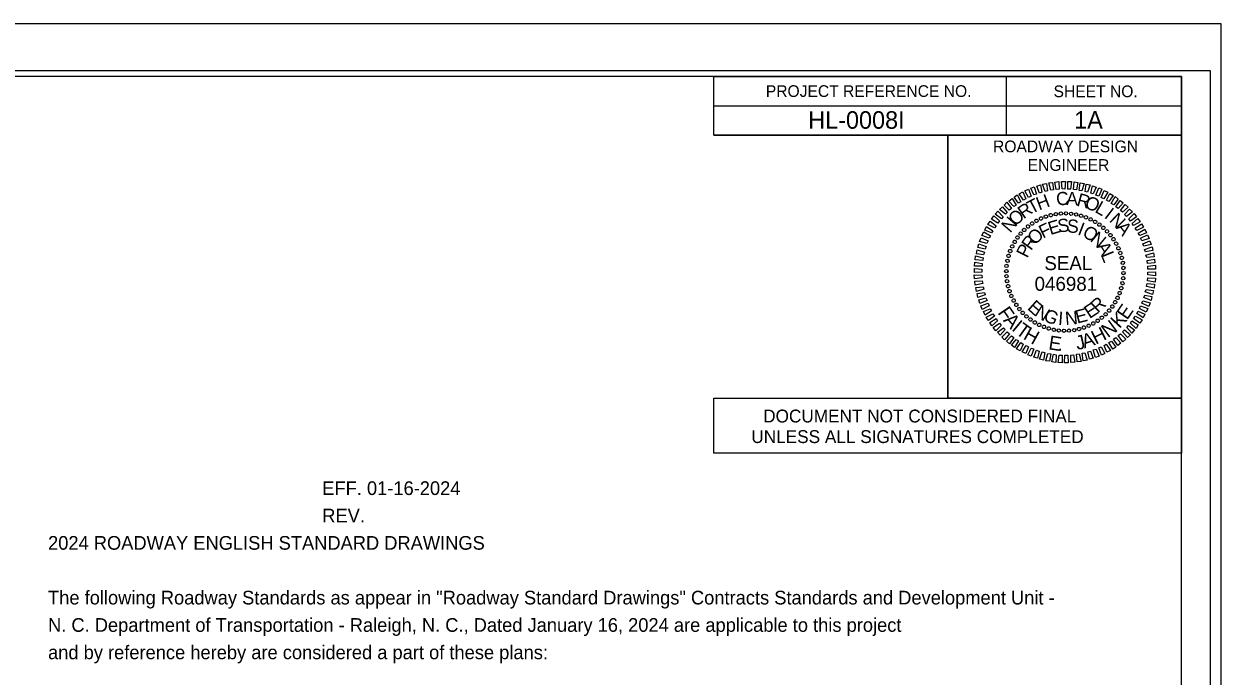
# Model space of a CAD drawing. Extents: x 3312684 to 3314684, y -677777 to -676682.
# Drawn here: x 3314171 to 3314684, y -676961 to -676682 of the extents above; entities that cross this region are included whole.
import ezdxf

# ---------------------------------------------------------------- set-up
doc = ezdxf.new("R2010")
doc.units = 0
for name, color, linetype in [('Default', 7, 'Continuous'), ('Sheet Data Field CELL', 7, 'Continuous'), ('Sheet PE Seal Cell', 7, 'Continuous'), ('Sheet Plan CELL', 7, 'Continuous'), ('Sheet Plot Border Inside CELL', 7, 'Continuous'), ('Sheet Plot Border Outside CELL', 7, 'Continuous'), ('Sheet Sticker Exception Certification CELL', 7, 'Continuous')]:
    doc.layers.add(name, color=color, linetype=linetype)

msp = doc.modelspace()

# ---------------------------------------------------------------- linework, layer by layer
at = {"layer": 'Sheet PE Seal Cell'}
for p, q in [((3314602.85, -676767.34), (3314602.85, -676767.34)), ((3314604.75, -676766.19), (3314604.75, -676766.19)), ((3314606.7, -676765.19), (3314606.7, -676765.19)), ((3314608.7, -676764.39), (3314608.7, -676764.39)), ((3314610.8, -676763.79), (3314610.8, -676763.79)), ((3314613, -676763.39), (3314613, -676763.39)), ((3314615.15, -676763.09), (3314615.15, -676763.09)), ((3314617.35, -676763.04), (3314617.35, -676763.04)), ((3314619.55, -676763.19), (3314619.55, -676763.19)), ((3314621.7, -676763.54), (3314621.7, -676763.54)), ((3314623.8, -676763.99), (3314623.8, -676763.99)), ((3314625.9, -676764.69), (3314625.9, -676764.69)), ((3314627.9, -676765.59), (3314627.9, -676765.59)), ((3314629.85, -676766.59), (3314629.85, -676766.59)), ((3314631.65, -676767.84), (3314631.65, -676767.84)), ((3314597.95, -676771.64), (3314597.95, -676771.64)), ((3314599.45, -676770.09), (3314599.45, -676770.09)), ((3314601.1, -676768.59), (3314601.1, -676768.59)), ((3314633.4, -676769.19), (3314633.4, -676769.19)), ((3314634.95, -676770.69), (3314634.95, -676770.69)), ((3314636.45, -676772.34), (3314636.45, -676772.34)), ((3314594.35, -676777.14), (3314594.35, -676777.14)), ((3314595.35, -676775.19), (3314595.35, -676775.19)), ((3314596.6, -676773.39), (3314596.6, -676773.39)), ((3314637.7, -676774.09), (3314637.7, -676774.09)), ((3314638.85, -676775.99), (3314638.85, -676775.99)), ((3314639.85, -676777.94), (3314639.85, -676777.94)), ((3314592.3, -676783.34), (3314592.3, -676783.34)), ((3314592.75, -676781.24), (3314592.75, -676781.24)), ((3314593.45, -676779.14), (3314593.45, -676779.14)), ((3314640.65, -676779.94), (3314640.65, -676779.94)), ((3314641.25, -676782.04), (3314641.25, -676782.04)), ((3314591.8, -676787.69), (3314591.8, -676787.69)), ((3314591.95, -676785.49), (3314591.95, -676785.49)), ((3314616.9, -676788.14), (3314616.9, -676788.14)), ((3314641.65, -676784.24), (3314641.65, -676784.24)), ((3314641.95, -676786.39), (3314641.95, -676786.39)), ((3314591.85, -676789.89), (3314591.85, -676789.89)), ((3314592.15, -676792.04), (3314592.15, -676792.04)), ((3314641.5, -676792.94), (3314641.5, -676792.94)), ((3314641.85, -676790.79), (3314641.85, -676790.79)), ((3314642, -676788.59), (3314642, -676788.59)), ((3314592.55, -676794.24), (3314592.55, -676794.24)), ((3314593.15, -676796.34), (3314593.15, -676796.34)), ((3314593.95, -676798.34), (3314593.95, -676798.34)), ((3314640.35, -676797.14), (3314640.35, -676797.14)), ((3314641.05, -676795.04), (3314641.05, -676795.04)), ((3314594.95, -676800.29), (3314594.95, -676800.29)), ((3314596.1, -676802.19), (3314596.1, -676802.19)), ((3314637.2, -676802.89), (3314637.2, -676802.89)), ((3314638.45, -676801.09), (3314638.45, -676801.09)), ((3314639.45, -676799.14), (3314639.45, -676799.14)), ((3314597.35, -676803.94), (3314597.35, -676803.94)), ((3314598.85, -676805.59), (3314598.85, -676805.59)), ((3314600.4, -676807.09), (3314600.4, -676807.09)), ((3314602.15, -676808.44), (3314602.15, -676808.44)), ((3314630.95, -676808.94), (3314630.95, -676808.94)), ((3314632.7, -676807.69), (3314632.7, -676807.69)), ((3314634.35, -676806.19), (3314634.35, -676806.19)), ((3314635.85, -676804.64), (3314635.85, -676804.64)), ((3314603.95, -676809.69), (3314603.95, -676809.69)), ((3314605.9, -676810.69), (3314605.9, -676810.69)), ((3314607.9, -676811.59), (3314607.9, -676811.59)), ((3314610, -676812.29), (3314610, -676812.29)), ((3314612.1, -676812.74), (3314612.1, -676812.74)), ((3314614.25, -676813.09), (3314614.25, -676813.09)), ((3314616.45, -676813.24), (3314616.45, -676813.24)), ((3314618.65, -676813.19), (3314618.65, -676813.19)), ((3314620.8, -676812.89), (3314620.8, -676812.89)), ((3314623, -676812.49), (3314623, -676812.49)), ((3314625.1, -676811.89), (3314625.1, -676811.89)), ((3314627.1, -676811.09), (3314627.1, -676811.09)), ((3314629.05, -676810.09), (3314629.05, -676810.09))]:
    msp.add_line(p, q, dxfattribs=at)
for points in [[(3314603.55, -676755.14), (3314602.25, -676752.24), (3314603.75, -676751.64), (3314604.8, -676754.84)], [(3314606, -676754.34), (3314604.85, -676751.34), (3314606.4, -676750.89), (3314607.05, -676753.99)], [(3314608.4, -676753.69), (3314607.35, -676750.54), (3314609.05, -676750.19), (3314609.45, -676753.44)], [(3314610.8, -676753.14), (3314610, -676749.94), (3314611.65, -676749.79), (3314612, -676752.99)], [(3314613.2, -676752.84), (3314612.65, -676749.64), (3314614.35, -676749.44), (3314614.4, -676752.69)], [(3314615.7, -676752.59), (3314615.45, -676749.34), (3314617.1, -676749.39), (3314616.9, -676752.64)], [(3314618.1, -676752.64), (3314618.1, -676749.39), (3314619.75, -676749.44), (3314619.3, -676752.69)], [(3314620.6, -676752.79), (3314620.8, -676749.54), (3314622.45, -676749.84), (3314621.8, -676752.99)], [(3314623, -676753.19), (3314623.45, -676749.99), (3314625.1, -676750.24), (3314624.2, -676753.34)], [(3314625.55, -676753.74), (3314626.05, -676750.49), (3314627.75, -676750.89), (3314626.6, -676753.99)], [(3314627.95, -676754.39), (3314628.7, -676751.29), (3314630.25, -676751.79), (3314629, -676754.74)], [(3314630.2, -676755.29), (3314631.35, -676752.14), (3314632.75, -676752.74), (3314631.35, -676755.64)], [(3314595.1, -676760.14), (3314592.95, -676757.74), (3314594.3, -676756.69), (3314596.05, -676759.49)], [(3314597, -676758.64), (3314595.15, -676756.09), (3314596.45, -676755.14), (3314598.1, -676758.04)], [(3314599.2, -676757.39), (3314597.35, -676754.69), (3314598.9, -676753.89), (3314600.15, -676756.79)], [(3314601.35, -676756.19), (3314599.75, -676753.39), (3314601.3, -676752.69), (3314602.45, -676755.74)], [(3314632.45, -676756.24), (3314633.7, -676753.29), (3314635.25, -676753.99), (3314633.55, -676756.79)], [(3314634.75, -676757.39), (3314636.1, -676754.54), (3314637.6, -676755.39), (3314635.7, -676757.99)], [(3314636.7, -676758.74), (3314638.45, -676755.84), (3314639.75, -676756.89), (3314637.8, -676759.34)], [(3314638.75, -676760.24), (3314640.6, -676757.49), (3314641.9, -676758.59), (3314639.7, -676760.94)], [(3314589.7, -676765.34), (3314587.1, -676763.39), (3314588.2, -676762.09), (3314590.4, -676764.44)], [(3314591.45, -676763.44), (3314588.9, -676761.39), (3314590.15, -676760.24), (3314592.25, -676762.64)], [(3314593.1, -676761.69), (3314590.9, -676759.49), (3314592.1, -676758.29), (3314594.05, -676760.99)], [(3314640.65, -676761.79), (3314642.7, -676759.19), (3314643.9, -676760.39), (3314641.6, -676762.54)], [(3314642.45, -676763.54), (3314644.6, -676761.19), (3314645.8, -676762.39), (3314643.2, -676764.34)], [(3314586.7, -676769.24), (3314583.9, -676767.74), (3314584.9, -676766.34), (3314587.5, -676768.34)], [(3314588.2, -676767.24), (3314585.5, -676765.54), (3314586.45, -676764.09), (3314588.85, -676766.29)], [(3314644.2, -676765.34), (3314646.5, -676763.09), (3314647.55, -676764.44), (3314644.9, -676766.34)], [(3314645.7, -676767.29), (3314648.15, -676765.19), (3314649.1, -676766.64), (3314646.3, -676768.24)], [(3314647, -676769.34), (3314649.65, -676767.44), (3314650.6, -676768.94), (3314647.7, -676770.34)], [(3314584.5, -676773.69), (3314581.4, -676772.54), (3314582.15, -676770.99), (3314585, -676772.59)], [(3314585.5, -676771.39), (3314582.65, -676770.14), (3314583.4, -676768.59), (3314586.1, -676770.44)], [(3314648.3, -676771.54), (3314651.1, -676769.79), (3314651.75, -676771.34), (3314648.9, -676772.49)], [(3314649.3, -676773.69), (3314652.25, -676772.19), (3314652.9, -676773.79), (3314649.8, -676774.79)], [(3314582.75, -676778.29), (3314579.65, -676777.64), (3314580, -676775.99), (3314583.15, -676777.24)], [(3314583.5, -676775.89), (3314580.4, -676774.99), (3314581.05, -676773.44), (3314584.05, -676774.84)], [(3314650.2, -676776.04), (3314653.25, -676774.74), (3314653.8, -676776.29), (3314650.7, -676777.09)], [(3314651, -676778.44), (3314654.2, -676777.29), (3314654.5, -676778.94), (3314651.35, -676779.49)], [(3314581.7, -676783.24), (3314578.5, -676782.94), (3314578.7, -676781.24), (3314581.95, -676782.04)], [(3314582.1, -676780.69), (3314579, -676780.29), (3314579.35, -676778.59), (3314582.5, -676779.64)], [(3314651.6, -676780.84), (3314654.75, -676779.89), (3314655.05, -676781.59), (3314651.9, -676781.89)], [(3314652.05, -676783.24), (3314655.3, -676782.54), (3314655.45, -676784.24), (3314652.25, -676784.44)], [(3314581.4, -676788.14), (3314578.15, -676788.29), (3314578.15, -676786.59), (3314581.4, -676786.94)], [(3314581.45, -676785.64), (3314578.2, -676785.54), (3314578.3, -676783.89), (3314581.55, -676784.44)], [(3314652.35, -676785.64), (3314655.6, -676785.24), (3314655.7, -676786.94), (3314652.45, -676786.84)], [(3314652.4, -676788.14), (3314655.65, -676787.99), (3314655.65, -676789.69), (3314652.4, -676789.34)], [(3314581.45, -676790.64), (3314578.2, -676791.04), (3314578.1, -676789.34), (3314581.35, -676789.44)], [(3314581.75, -676793.04), (3314578.5, -676793.74), (3314578.35, -676792.04), (3314581.55, -676791.84)], [(3314652.1, -676793.04), (3314655.3, -676793.34), (3314655.1, -676795.04), (3314651.85, -676794.24)], [(3314652.35, -676790.64), (3314655.6, -676790.74), (3314655.5, -676792.39), (3314652.25, -676791.84)], [(3314582.2, -676795.44), (3314579.05, -676796.39), (3314578.75, -676794.69), (3314581.9, -676794.39)], [(3314582.8, -676797.84), (3314579.6, -676798.99), (3314579.3, -676797.34), (3314582.45, -676796.79)], [(3314651.05, -676797.99), (3314654.15, -676798.64), (3314653.8, -676800.29), (3314650.65, -676799.04)], [(3314651.7, -676795.59), (3314654.8, -676795.99), (3314654.45, -676797.69), (3314651.3, -676796.64)], [(3314583.6, -676800.24), (3314580.55, -676801.54), (3314580, -676799.99), (3314583.1, -676799.19)], [(3314584.5, -676802.59), (3314581.55, -676804.09), (3314580.9, -676802.49), (3314584, -676801.49)], [(3314585.5, -676804.74), (3314582.7, -676806.49), (3314582.05, -676804.94), (3314584.9, -676803.79)], [(3314649.3, -676802.59), (3314652.4, -676803.74), (3314651.65, -676805.29), (3314648.8, -676803.69)], [(3314650.3, -676800.39), (3314653.4, -676801.29), (3314652.75, -676802.84), (3314649.75, -676801.44)], [(3314586.8, -676806.94), (3314584.15, -676808.84), (3314583.2, -676807.34), (3314586.1, -676805.94)], [(3314588.1, -676808.99), (3314585.65, -676811.09), (3314584.7, -676809.64), (3314587.5, -676808.04)], [(3314645.6, -676809.04), (3314648.3, -676810.74), (3314647.35, -676812.19), (3314644.95, -676809.99)], [(3314647.1, -676807.04), (3314649.9, -676808.54), (3314648.9, -676809.94), (3314646.3, -676807.94)], [(3314648.3, -676804.89), (3314651.15, -676806.14), (3314650.4, -676807.69), (3314647.7, -676805.84)], [(3314589.6, -676810.94), (3314587.3, -676813.19), (3314586.25, -676811.84), (3314588.9, -676809.94)], [(3314591.35, -676812.74), (3314589.2, -676815.09), (3314588, -676813.89), (3314590.6, -676811.94)], [(3314593.15, -676814.49), (3314591.1, -676817.09), (3314589.9, -676815.89), (3314592.2, -676813.74)], [(3314642.35, -676812.84), (3314644.9, -676814.89), (3314643.65, -676816.04), (3314641.55, -676813.64)], [(3314644.1, -676810.94), (3314646.7, -676812.89), (3314645.6, -676814.19), (3314643.4, -676811.84)], [(3314595.05, -676816.04), (3314593.2, -676818.79), (3314591.9, -676817.69), (3314594.1, -676815.34)], [(3314597.1, -676817.54), (3314595.35, -676820.44), (3314594.05, -676819.39), (3314596, -676816.94)], [(3314599.05, -676818.89), (3314597.7, -676821.74), (3314596.2, -676820.89), (3314598.1, -676818.29)], [(3314634.6, -676818.89), (3314636.45, -676821.59), (3314634.9, -676822.39), (3314633.65, -676819.49)], [(3314636.8, -676817.64), (3314638.65, -676820.19), (3314637.35, -676821.14), (3314635.7, -676818.24)], [(3314638.7, -676816.14), (3314640.85, -676818.54), (3314639.5, -676819.59), (3314637.75, -676816.79)], [(3314640.7, -676814.59), (3314642.9, -676816.79), (3314641.7, -676817.99), (3314639.75, -676815.29)], [(3314601.35, -676820.04), (3314600.1, -676822.99), (3314598.55, -676822.29), (3314600.25, -676819.49)], [(3314603.6, -676820.99), (3314602.45, -676824.14), (3314601.05, -676823.54), (3314602.45, -676820.64)], [(3314605.85, -676821.89), (3314605.1, -676824.99), (3314603.55, -676824.49), (3314604.8, -676821.54)], [(3314608.25, -676822.54), (3314607.75, -676825.79), (3314606.05, -676825.39), (3314607.2, -676822.29)], [(3314610.8, -676823.09), (3314610.35, -676826.29), (3314608.7, -676826.04), (3314609.6, -676822.94)], [(3314613.2, -676823.49), (3314613, -676826.74), (3314611.35, -676826.44), (3314612, -676823.29)], [(3314615.7, -676823.64), (3314615.7, -676826.89), (3314614.05, -676826.84), (3314614.5, -676823.59)], [(3314618.1, -676823.69), (3314618.35, -676826.94), (3314616.7, -676826.89), (3314616.9, -676823.64)], [(3314620.6, -676823.44), (3314621.15, -676826.64), (3314619.45, -676826.84), (3314619.4, -676823.59)], [(3314623, -676823.14), (3314623.8, -676826.34), (3314622.15, -676826.49), (3314621.8, -676823.29)], [(3314625.4, -676822.59), (3314626.45, -676825.74), (3314624.75, -676826.09), (3314624.35, -676822.84)], [(3314627.8, -676821.94), (3314628.95, -676824.94), (3314627.4, -676825.39), (3314626.75, -676822.29)], [(3314630.25, -676821.14), (3314631.55, -676824.04), (3314630.05, -676824.64), (3314629, -676821.44)], [(3314632.45, -676820.09), (3314634.05, -676822.89), (3314632.5, -676823.59), (3314631.35, -676820.54)]]:
    msp.add_lwpolyline(points, close=True, dxfattribs=at)
for centre, major_axis in [((3314612.97, -676763.37), (-0.113, 0.711)), ((3314615.15, -676763.12), (-0.05, 0.718)), ((3314617.33, -676763.06), (0.013, 0.72)), ((3314619.52, -676763.19), (0.075, 0.716)), ((3314621.68, -676763.52), (0.137, 0.707)), ((3314601.11, -676768.65), (-0.453, 0.56)), ((3314602.87, -676767.34), (-0.403, 0.597)), ((3314604.74, -676766.2), (-0.349, 0.63)), ((3314606.69, -676765.22), (-0.293, 0.658)), ((3314608.73, -676764.42), (-0.234, 0.681)), ((3314610.83, -676763.8), (-0.174, 0.699)), ((3314623.81, -676764.03), (0.198, 0.692)), ((3314625.88, -676764.72), (0.258, 0.672)), ((3314627.89, -676765.59), (0.316, 0.647)), ((3314629.81, -676766.64), (0.371, 0.617)), ((3314631.64, -676767.85), (0.423, 0.582)), ((3314596.61, -676773.39), (-0.582, 0.423)), ((3314597.97, -676771.68), (-0.543, 0.472)), ((3314599.47, -676770.1), (-0.5, 0.518)), ((3314633.35, -676769.21), (0.472, 0.543)), ((3314634.94, -676770.71), (0.518, 0.5)), ((3314636.39, -676772.35), (0.56, 0.453)), ((3314594.35, -676777.14), (-0.647, 0.316)), ((3314595.4, -676775.22), (-0.617, 0.371)), ((3314637.69, -676774.11), (0.597, 0.403)), ((3314638.83, -676775.98), (0.63, 0.349)), ((3314639.81, -676777.94), (0.658, 0.293)), ((3314592.28, -676783.35), (-0.707, 0.137)), ((3314592.79, -676781.22), (-0.692, 0.198)), ((3314593.48, -676779.15), (-0.672, 0.258)), ((3314640.61, -676779.97), (0.681, 0.234)), ((3314641.23, -676782.07), (0.699, 0.174)), ((3314591.82, -676787.7), (-0.72, 0.013)), ((3314591.95, -676785.51), (-0.716, 0.075)), ((3314641.67, -676784.21), (0.711, 0.113)), ((3314641.91, -676786.39), (0.718, 0.05)), ((3314641.97, -676788.57), (0.72, -0.013)), ((3314591.88, -676789.89), (-0.718, -0.05)), ((3314592.12, -676792.06), (-0.711, -0.113)), ((3314592.56, -676794.2), (-0.699, -0.174)), ((3314641.51, -676792.92), (0.707, -0.137)), ((3314641.84, -676790.76), (0.716, -0.075)), ((3314593.18, -676796.3), (-0.681, -0.234)), ((3314593.98, -676798.34), (-0.658, -0.293)), ((3314639.44, -676799.13), (0.647, -0.316)), ((3314640.31, -676797.12), (0.672, -0.258)), ((3314641, -676795.05), (0.692, -0.198)), ((3314594.96, -676800.3), (-0.63, -0.349)), ((3314596.1, -676802.16), (-0.597, -0.403)), ((3314597.4, -676803.92), (-0.56, -0.453)), ((3314635.82, -676804.59), (0.543, -0.472)), ((3314637.19, -676802.88), (0.582, -0.423)), ((3314638.39, -676801.05), (0.617, -0.371)), ((3314598.85, -676805.56), (-0.518, -0.5)), ((3314600.44, -676807.06), (-0.472, -0.543)), ((3314602.15, -676808.43), (-0.423, -0.582)), ((3314603.98, -676809.63), (-0.371, -0.617)), ((3314630.92, -676808.93), (0.403, -0.597)), ((3314632.68, -676807.63), (0.453, -0.56)), ((3314634.32, -676806.18), (0.5, -0.518)), ((3314605.9, -676810.68), (-0.316, -0.647)), ((3314607.91, -676811.55), (-0.258, -0.672)), ((3314609.98, -676812.24), (-0.198, -0.692)), ((3314612.11, -676812.76), (-0.137, -0.707)), ((3314614.27, -676813.08), (-0.075, -0.716)), ((3314616.46, -676813.21), (-0.013, -0.72)), ((3314618.64, -676813.16), (0.05, -0.718)), ((3314620.82, -676812.91), (0.113, -0.711)), ((3314622.96, -676812.47), (0.174, -0.699)), ((3314625.06, -676811.85), (0.234, -0.681)), ((3314627.1, -676811.05), (0.293, -0.658)), ((3314629.05, -676810.07), (0.349, -0.63))]:
    msp.add_ellipse(centre, major_axis=major_axis, ratio=0.999708, dxfattribs=at)
at = {"layer": 'Sheet Plan CELL'}
for p, q in [((3314591.73, -676704.6), (3314591.73, -676729.6)), ((3314466.68, -676717.1), (3314666.73, -676717.1)), ((3314466.68, -676729.6), (3314666.73, -676729.6)), ((3314466.68, -676729.6), (3314666.73, -676729.6)), ((3314566.73, -676729.6), (3314566.73, -676842.05))]:
    msp.add_line(p, q, dxfattribs=at)
for points in [[(3314666.73, -676704.55), (3313166.73, -676704.55), (3313166.73, -677754.55), (3314666.73, -677754.55)], [(3314466.68, -676704.55), (3314666.73, -676704.55), (3314666.73, -676729.6), (3314466.68, -676729.6)], [(3314566.73, -676729.6), (3314666.73, -676729.6), (3314666.73, -676842.1), (3314566.73, -676842.1)]]:
    msp.add_lwpolyline(points, close=True, dxfattribs=at)
at = {"layer": 'Sheet Plot Border Inside CELL'}
msp.add_lwpolyline([(3313013.23, -677757.05), (3314679.23, -677757.05), (3314679.23, -676702.05), (3313013.23, -676702.05)], close=True, dxfattribs=at)
at = {"layer": 'Sheet Plot Border Outside CELL'}
msp.add_lwpolyline([(3313000.23, -677777.05), (3314683.73, -677777.05), (3314683.73, -676682.05), (3313000.23, -676682.05)], close=True, dxfattribs=at)
at = {"layer": 'Sheet Sticker Exception Certification CELL'}
for p, q in [((3314466.69, -676865.59), (3314466.69, -676842.09)), ((3314466.69, -676842.09), (3314666.73, -676842.09)), ((3314666.73, -676842.1), (3314666.73, -676865.6)), ((3314666.73, -676865.59), (3314466.69, -676865.59))]:
    msp.add_line(p, q, dxfattribs=at)

# ---------------------------------------------------------------- texts
at = {"layer": 'Default'}
for s, p in [('                                                      EFF. 01-16-2024', (3314181.69, -676883.44)), ('                                                      REV. ', (3314181.69, -676895.14)), ('2024 ROADWAY ENGLISH STANDARD DRAWINGS', (3314181.69, -676906.84)), ('The following Roadway Standards as appear in "Roadway Standard Drawings" Contracts Standards and Development Unit -', (3314181.69, -676930.24)), ('N. C. Department of Transportation - Raleigh, N. C., Dated January 16, 2024 are applicable to this project', (3314181.69, -676941.94)), ('and by reference hereby are considered a part of these plans:', (3314181.69, -676953.64))]:
    msp.add_text(s, height=5.85, dxfattribs=at).set_placement(p)
at = {"layer": 'Sheet Data Field CELL'}
for s, p in [('HL-0008I', (3314507.03, -676726.85)), ('1A ', (3314620.84, -676726.8))]:
    msp.add_text(s, height=7.5, dxfattribs=at).set_placement(p)
at = {"layer": 'Sheet PE Seal Cell'}
for s, height, rotation, p in [('T', 5.64, 27.8198, (3314602.6, -676763.44)), ('H', 5.64, 20.6195, (3314605.85, -676761.79)), ('C', 5.64, 6.2199, (3314613.45, -676759.79)), ('A', 5.64, 359.0203, (3314617.4, -676759.49)), ('R', 5.64, 344.6211, (3314621.6, -676759.69)), ('O', 5.64, 337.4212, (3314624.95, -676760.44)), ('L', 5.64, 330.2209, (3314629.35, -676762.29)), ('O', 5.64, 42.2217, (3314595.75, -676768.74)), ('R', 5.64, 35.0205, (3314599.2, -676765.64)), ('I', 5.64, 323.0201, (3314633.4, -676764.69)), ('N', 5.64, 315.8189, (3314635.55, -676766.24)), ('N', 5.64, 49.4235, (3314593.45, -676771.64)), ('F', 5.64, 25.967, (3314607.45, -676773.84)), ('E', 5.64, 16.6111, (3314610.65, -676772.34)), ('S', 5.64, 7.2556, (3314614.1, -676771.29)), ('S', 5.64, 357.9004, (3314617.7, -676771.24)), ('I', 5.64, 339.1896, (3314622, -676771.94)), ('A', 5.64, 308.6172, (3314638.5, -676769.19)), ('R', 5.64, 54.0397, (3314602.4, -676779.24)), ('O', 5.64, 44.6812, (3314604.15, -676776.79)), ('O', 5.64, 329.8335, (3314624, -676772.64)), ('N', 5.64, 320.4766, (3314627.35, -676774.64)), ('P', 5.64, 63.3989, (3314600.8, -676782.44)), ('A', 5.64, 301.7603, (3314630.2, -676777.24)), ('SEAL', 5.998, 360, (3314608.1, -676787.29)), ('L', 5.64, 292.4008, (3314632.15, -676780.69)), ('F', 6, 304.4142, (3314587.93, -676805.48)), ('E', 5.64, 318.2769, (3314600.5, -676803.79)), ('N', 5.64, 327.634, (3314603.5, -676806.49)), ('E', 5.64, 14.4118, (3314622.15, -676810.19)), ('E', 5.64, 33.1241, (3314627.45, -676808.24)), ('R', 5.64, 42.4814, (3314631, -676805.89)), ('E', 6, 55.493, (3314643.5, -676808.93)), ('A', 6, 311.4309, (3314590.26, -676808.89)), ('I', 6, 320.2712, (3314593.77, -676812.74)), ('G', 5.64, 336.9902, (3314607.3, -676808.74)), ('I', 5.64, 355.7012, (3314613.85, -676810.64)), ('N', 5.64, 5.0564, (3314617.2, -676810.79)), ('N', 6, 36.4833, (3314635.27, -676816.46)), ('K', 6, 47.2091, (3314640.22, -676812.54)), ('T', 6, 324.0731, (3314595.45, -676814.22)), ('H', 6, 330.8733, (3314598.69, -676816.57)), ('H', 6, 26.4993, (3314630.09, -676819.22)), ('E', 6, 351.0577, (3314609.62, -676821.11)), ('J', 6, 12.4012, (3314622.12, -676821.49)), ('A', 6, 17.659, (3314625.15, -676820.87)), ('.', 6, 358.167, (3314613.76, -676821.75))]:
    msp.add_text(s, height=height, rotation=rotation, dxfattribs=at).set_placement(p)
msp.add_text('046981', height=5.998, dxfattribs=at).set_placement((3314603.92, -676796.14))
at = {"layer": 'Sheet Plan CELL'}
for s, height, p in [('PROJECT REFERENCE NO.', 5.0001, (3314488.88, -676713.25)), ('SHEET NO.', 5, (3314612.03, -676713.35)), ('ROADWAY DESIGN', 5.0001, (3314586.13, -676736.9)), ('ENGINEER', 5, (3314600.98, -676744.85))]:
    msp.add_text(s, height=height, dxfattribs=at).set_placement(p)
at = {"layer": 'Sheet Sticker Exception Certification CELL'}
for s, p in [('DOCUMENT NOT CONSIDERED FINAL', (3314487.76, -676852.43)), ('UNLESS ALL SIGNATURES COMPLETED', (3314482.69, -676861.23))]:
    msp.add_text(s, height=5.5, dxfattribs=at).set_placement(p)

doc.saveas('drawing.dxf')
